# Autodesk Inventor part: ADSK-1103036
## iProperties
Shininess: 41.0
Length Units: 11272
Angle Units: 11279
Time Units: 11290
Mass Units: 11286
Length Display Precision: 4
Angle Display Precision: 2
Compacted: True
Created: 2000-08
Part Number: ADSK-1103036
Document SubType Name: Modeling
Description: COUPLING - REAR
Mass: 2.93289 g
Surface Area: 23.8327 cm^2
Volume: 2.34631 cm^3
Density: 1.25 g/cm^3
Material: Silicone
Density: 0.0
Volumn: 0.0
Area: 0.0
PropertySet Name: Model Information
Control State: 0
Master: False
Checked Out: False
Author: Autodesk, Inc.
